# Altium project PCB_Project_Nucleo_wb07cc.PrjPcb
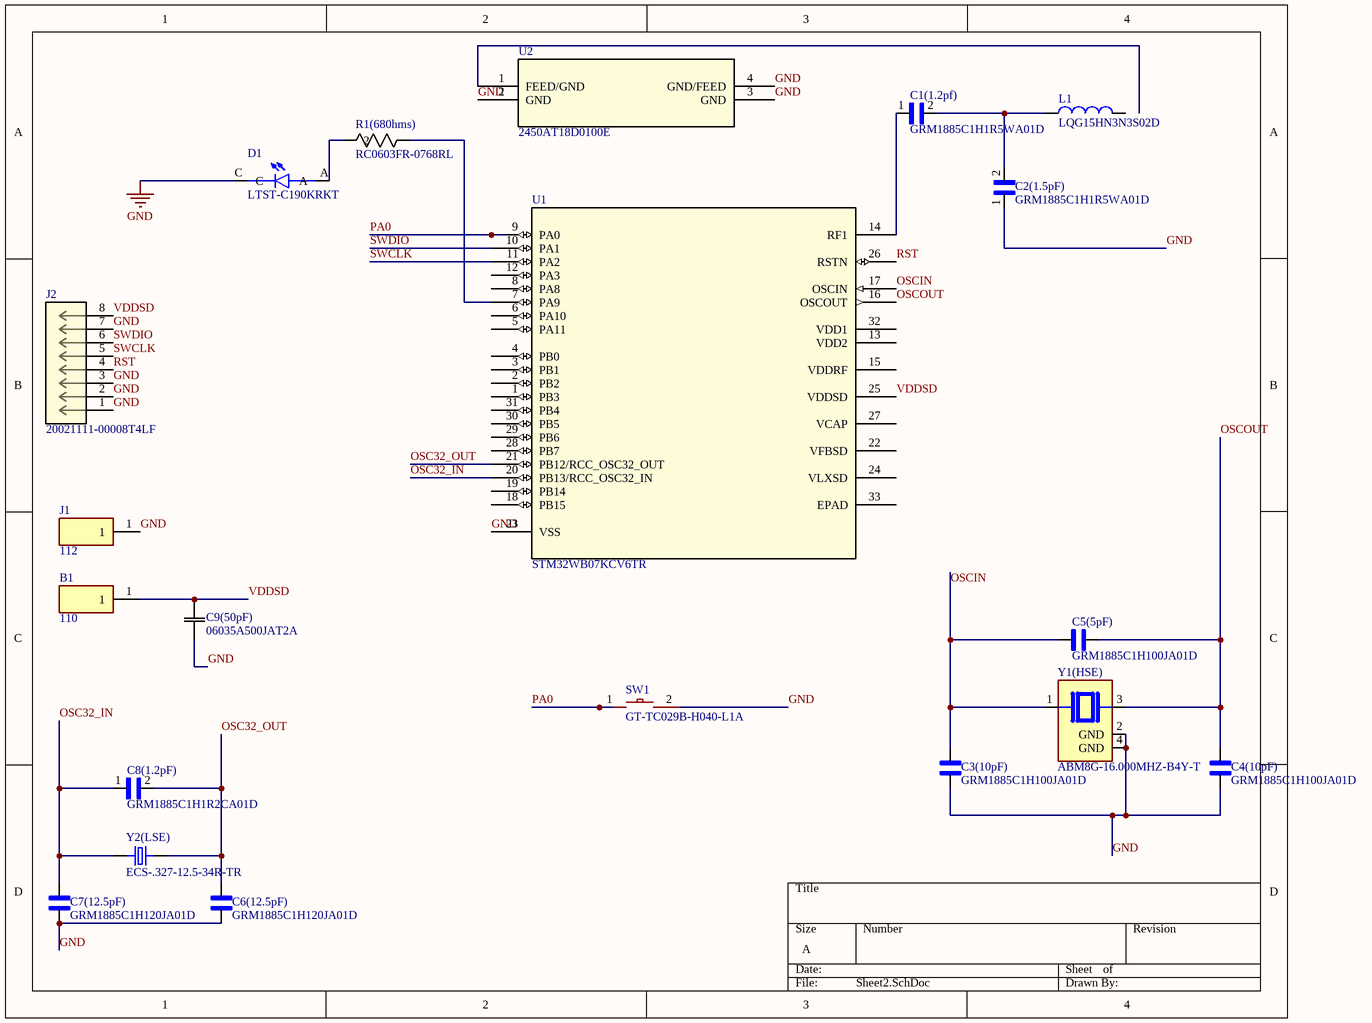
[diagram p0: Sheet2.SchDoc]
1 sheet, 20 parts. Net scope: global (net labels, ports and power ports of the same name join across sheets).
Board file: Sheet2.PcbDoc

## Sheet Sheet2.SchDoc
size A; SheetNumber: 1; SheetTotal: 1

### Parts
B1  110  [110]
C1(1.2pf)  GRM1885C1H1R5WA01D  [CAPC1608X90N]
C2(1.5pF)  GRM1885C1H1R5WA01D  [CAPC1608X90N]
C3(10pF)  GRM1885C1H100JA01D  [CAPC1608X90N]
C4(10pF)  GRM1885C1H100JA01D  [CAPC1608X90N]
C5(5pF)  GRM1885C1H100JA01D  [CAPC1608X90N]
C6(12.5pF)  GRM1885C1H120JA01D  [CAPC1608X90N]
C7(12.5pF)  GRM1885C1H120JA01D  [CAPC1608X90N]
C8(1.2pF)  GRM1885C1H1R2CA01D  [CAPC1608X90N]
C9(50pF)  06035A500JAT2A  [CAP_06033D104JAT2A]
D1  LTST-C190KRKT  [LEDC1608X35N]
J1  112  [112]
J2  20021111-00008T4LF  [CONN_20021111-00008T4LF_AMP]
L1  LQG15HN3N3S02D  [INDC1005X55N]
R1(680hms)  RC0603FR-0768RL  [RC0603N_YAG]
SW1  GT-TC029B-H040-L1A  [SW-SMD_L4.0-W3.0-LS4.8-EH]
U1  STM32WB07KCV6TR  [VFQFPN-32_STM]
U2  2450AT18D0100E  [2450AT18D0100E_JOT]
Y1(HSE)  ABM8G-16.000MHZ-B4Y-T  [XTAL_ABM8G-16.000MHZ-B4Y-T]
Y2(LSE)  ECS-.327-12.5-34R-TR  [XTAL_ECS-.327-12.5-34R-TR]

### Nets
GND: C2(1.5pF).1 C3(10pF).1 C4(10pF).1 C6(12.5pF).1 C7(12.5pF).1 C9(50pF).1(EPAD) D1.C J1.1 J2.1 J2.2 J2.3 J2.7 SW1.2 U1.23(VSS) U2.2(GND) U2.3(GND) U2.4(GND/FEED) Y1(HSE).2(GND) Y1(HSE).4(GND)
OSC32_IN: C7(12.5pF).2 C8(1.2pF).1 U1.20(PB13/RCC_OSC32_IN) Y2(LSE).1(IN/OUT)
OSC32_OUT: C6(12.5pF).2 C8(1.2pF).2 U1.21(PB12/RCC_OSC32_OUT) Y2(LSE).2(OUT/IN)
OSCIN: C3(10pF).2 C5(5pF).1 U1.17(OSCIN) Y1(HSE).1
OSCOUT: C4(10pF).2 C5(5pF).2 U1.16(OSCOUT) Y1(HSE).3
PA0: SW1.1 U1.9(PA0)
RST: J2.4 U1.26(RSTN)
SWCLK: J2.5 U1.11(PA2)
SWDIO: J2.6 U1.10(PA1)
VDDSD: B1.1 C9(50pF).2(EPAD) J2.8 U1.25(VDDSD)
NetC1(1.2pf)_1: C1(1.2pf).1 U1.14(RF1)
NetC1(1.2pf)_2: C1(1.2pf).2 C2(1.5pF).2 L1.1
NetD1_A: D1.A R1(680hms).2
NetR1(680hms)_1: R1(680hms).1 U1.7(PA9)

Not connected (* = marked no-connect by the designer): L1 2; U1 1(PB3) 2(PB2) 3(PB1) 4(PB0) 5(PA11) 6(PA10) 8(PA8) 12(PA3) 13(VDD2) 15(VDDRF) 18(PB15) 19(PB14) 22(VFBSD) 24(VLXSD) 27(VCAP) 28(PB7) 29(PB6) 30(PB5) 31(PB4) 32(VDD1) 33(EPAD); U2 1(FEED/GND)

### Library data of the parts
B1 = 110: Battery Contacts S/M COIN CELL CNCT POSITIVE 16mm UP; Manufacturer_Name: Keystone Electronics; Geometry.Height: 3.3mm
C1(1.2pf) C2(1.5pF) = GRM1885C1H1R5WA01D: CAP 1.5PF 50VDC C0G 0.05PF SMD 0603 PAPER TAPE
C3(10pF) C4(10pF) C5(5pF) = GRM1885C1H100JA01D: SMD Capacitor C0G(EIA) with Capacitance: 10pF Tol. 5%. Rated Voltage: 50Vdc; MF: Murata Electronics
C6(12.5pF) C7(12.5pF) = GRM1885C1H120JA01D: SMD Capacitor C0G(EIA) with Capacitance: 12pF Tol. 5%. Rated Voltage: 50Vdc; MF: Murata Electronics
C8(1.2pF) = GRM1885C1H1R2CA01D: CAP, MLCC, C0G/NP0, 1.2PF, 50V, 0603
C9(50pF) = 06035A500JAT2A: No Description Available; Manufacturer_Name: KYOCERA AVX
D1 = LTST-C190KRKT: Red 631nm LED Indication - Discrete 2V 0603 (1608 Metric); MF: Lite-On Inc.
J1 = 112: Battery Contacts S/M COIN CELL CNCT NEGATIVE 16mm UP; Manufacturer_Name: Keystone Electronics; Geometry.Height: 3mm
J2 = 20021111-00008T4LF: No Description Available; Mfr_Name: Amphenol ICC
L1 = LQG15HN3N3S02D: INDUCTOR, 0402 CASE, 3.3NHÂ±0.3NH; Inductance:3.3nH; Inductance Tolerance:Â± 0.3nH; DC Resistance Max:0.19ohm; DC Current Rating:300mA; Q Factor:8; Self Resonant Frequency:6GHz; Q Test Frequency:100MHz; Core Material:Air; Inductor Case Style:0402; No. of Pins:2; SVHC:No SVHC (19-Dec-2011); DC Current Max:300mA; Inductance Measurement Frequency:100MHz; Inductor Type:Monolithic; Operating Temperature Max:125Â°C; Operating Temperature Min:-55Â°C; Package / Case:0402; Q @ Vr F:8; Q Factor @ Frequency:8 @ 100MHz; Resistance:0.19ohm; Resonant Frequency:6GHz; Tolerance +:9.09%; Tolerance -:9.09%
R1(680hms) = RC0603FR-0768RL: No Description Available; Manufacturer_Name: Yageo
SW1 = GT-TC029B-H040-L1A: Manufacturer: G-Switch(品赞); Add into BOM: yes; Circuit: SPST; Actuator Style: Round Button; Operating Force: 250gf; Switch Length: 4mm; Switch Width: 3mm; Strike Gundam: Without; Contact Current: 50mA; Voltage Rating (DC): 12V; Insulation Resistance: 100MΩ; With Lamp: None; Pin Style: SMDSplicing; Mechanical Life: 100,000 Times
U1 = STM32WB07KCV6TR: Ultra-low-power, Arm Cortex-M0+ MCU 64 MHz with 256 Kbytes of Flash memory, 64 Kbytes of RAM,  Bluetooth LE 5.4; Manufacturer_Name: STMicroelectronics
U2 = 2450AT18D0100E: No Description Available; Manufacturer_Name: Johanson Technology
Y1(HSE) = ABM8G-16.000MHZ-B4Y-T: 16 MHz Â±30ppm Kristal 10pF 80 Ohm 4-SMD, KurÅŸunsuz; MF: Abracon
Y2(LSE) = ECS-.327-12.5-34R-TR: 32.768 kHz Â±20ppm Crystal 12.5pF 50 kOhms 2-SMD, No Lead; MF: ECS Inc.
